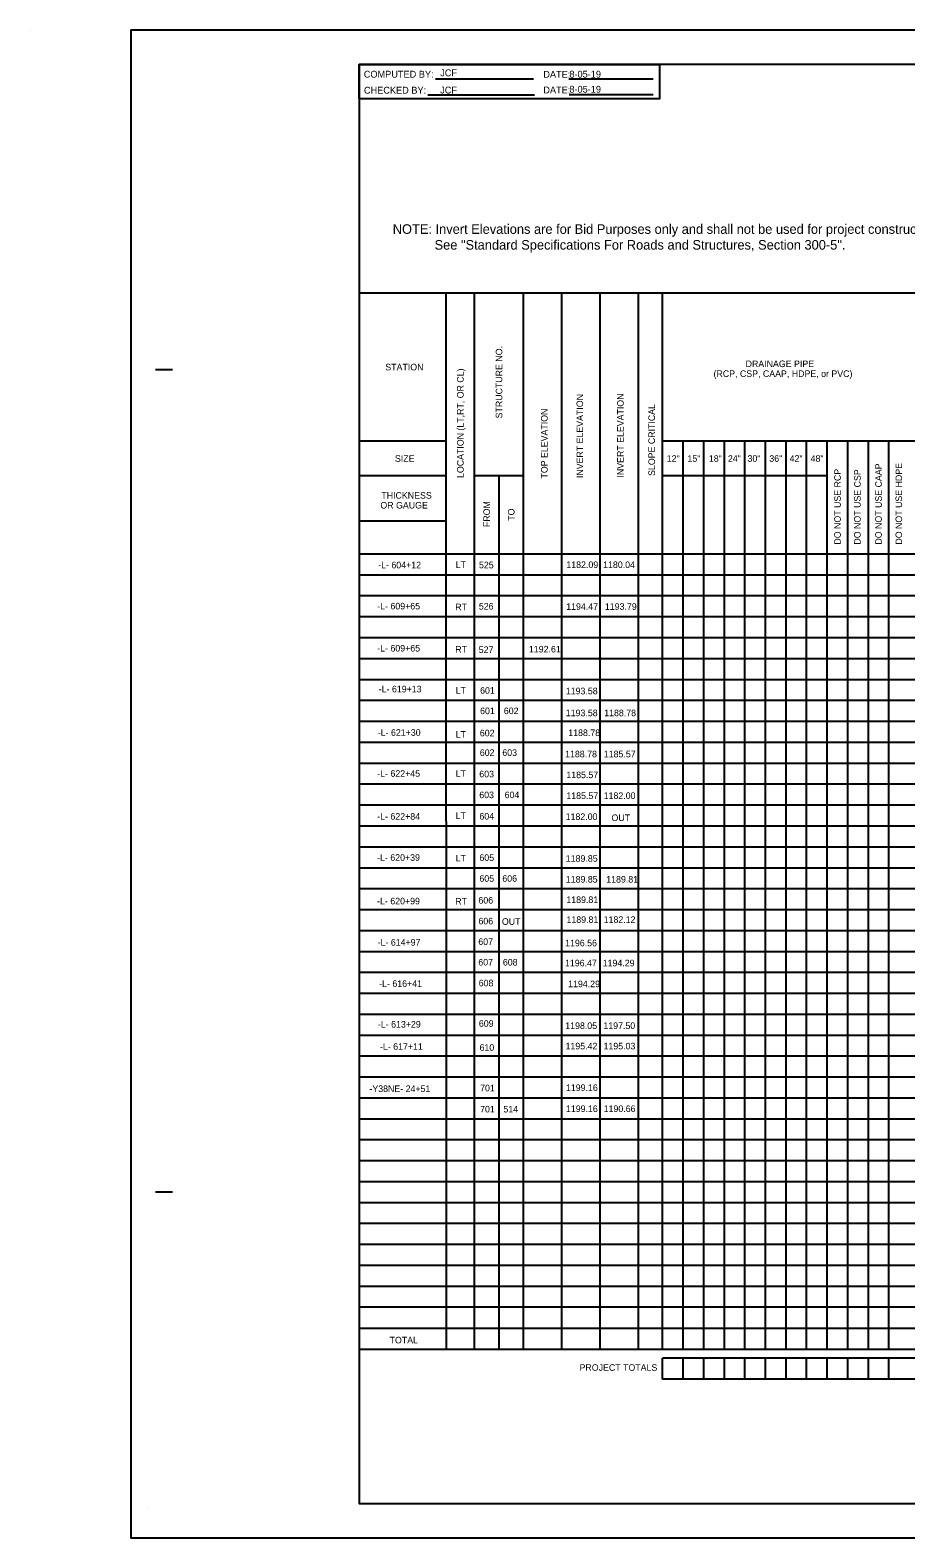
# Model space of a CAD drawing. Extents: x 809447 to 814738, y 647528 to 651206.
# Drawn here: x 812955 to 813593, y 650017 to 651117 of the extents above; entities that cross this region are included whole.
import ezdxf

# ---------------------------------------------------------------- set-up
doc = ezdxf.new("R2010")
doc.units = 0
doc.layers.add('Default', color=7, linetype='Continuous')

msp = doc.modelspace()

# ---------------------------------------------------------------- linework, layer by layer
at = {"layer": 'Default'}
for p, q in [((812954.7, 651116.9), (812954.7, 651116.9)), ((812954.7, 651116.9), (812954.7, 651116.9)), ((812954.7, 651116.9), (812954.7, 651116.9)), ((813250.2, 651081.5), (813321.8, 651081.5)), ((813347.6, 651081.4), (813409, 651081.4)), ((813244.8, 651069.8), (813322.5, 651069.8)), ((813347.7, 651069.9), (813409.1, 651069.9)), ((814694.6, 650925.1), (813194.6, 650925)), ((813258.2, 650154.3), (813258.1, 650925)), ((813278.7, 650154.3), (813278.7, 650925)), ((813314.5, 650154.3), (813314.4, 650925)), ((813342.5, 650154.3), (813342.4, 650925)), ((813370.4, 650154.3), (813370.4, 650925)), ((813398.4, 650154.3), (813398.4, 650925)), ((813415.9, 650154.3), (813415.9, 650925)), ((813046.1, 650869.4), (813058.6, 650869.4)), ((813258.1, 650817.1), (813194.6, 650817.1)), ((813933.4, 650817.2), (813415.9, 650817.1)), ((813430.9, 650154.3), (813430.9, 650817.1)), ((813445.9, 650154.3), (813445.9, 650817.1)), ((813460.9, 650154.3), (813460.9, 650817.1)), ((813475.9, 650154.3), (813475.9, 650817.1)), ((813490.9, 650154.3), (813490.9, 650817.1)), ((813505.9, 650154.3), (813505.9, 650817.1)), ((813520.9, 650154.3), (813520.9, 650817.1)), ((813535.9, 650154.3), (813535.9, 650817.1)), ((813550.9, 650154.3), (813550.9, 650817.1)), ((813565.9, 650154.3), (813565.9, 650817.1)), ((813580.9, 650154.3), (813580.9, 650817.1)), ((813258.1, 650791.7), (813194.6, 650791.7)), ((813314.5, 650791.7), (813278.7, 650791.7)), ((813296.6, 650154.3), (813296.6, 650791.7)), ((813535.9, 650791.8), (813415.9, 650791.7)), ((813258.1, 650758.6), (813194.6, 650758.6)), ((814694.6, 650734.7), (813194.6, 650734.7)), ((814694.6, 650719.4), (813194.6, 650719.4)), ((814694.6, 650704.1), (813194.6, 650704.1)), ((814694.6, 650688.9), (813194.6, 650688.9)), ((814694.6, 650673.6), (813194.6, 650673.6)), ((814694.6, 650658.3), (813194.6, 650658.3)), ((814694.6, 650643), (813194.6, 650643)), ((814694.6, 650627.8), (813194.6, 650627.8)), ((814694.6, 650612.5), (813194.6, 650612.5)), ((814694.6, 650597.3), (813194.6, 650597.3)), ((814694.6, 650582), (813194.6, 650582)), ((814694.6, 650566.7), (813194.6, 650566.7)), ((814694.6, 650551.5), (813194.6, 650551.5)), ((814694.6, 650536.2), (813194.6, 650536.2)), ((814694.6, 650520.9), (813194.6, 650520.9)), ((814694.6, 650505.6), (813194.6, 650505.6)), ((814694.6, 650490.4), (813194.6, 650490.4)), ((814694.6, 650475.1), (813194.6, 650475.1)), ((814694.6, 650459.8), (813194.6, 650459.8)), ((814694.6, 650444.5), (813194.6, 650444.5)), ((814694.6, 650429.3), (813194.6, 650429.3)), ((814694.6, 650414), (813194.6, 650414)), ((814694.6, 650398.8), (813194.6, 650398.8)), ((814694.6, 650383.5), (813194.6, 650383.5)), ((814694.6, 650368.3), (813194.6, 650368.3)), ((814694.6, 650353), (813194.6, 650353)), ((814694.6, 650337.8), (813194.6, 650337.8)), ((814694.6, 650322.5), (813194.6, 650322.5)), ((814694.6, 650307.2), (813194.6, 650307.2)), ((814694.6, 650291.9), (813194.6, 650291.9)), ((814694.6, 650276.7), (813194.6, 650276.7)), ((813046.1, 650269.4), (813058.6, 650269.4)), ((814694.6, 650261.4), (813194.6, 650261.4)), ((814694.6, 650246.2), (813194.6, 650246.2)), ((814694.6, 650230.9), (813194.6, 650230.9)), ((814694.6, 650215.7), (813194.6, 650215.7)), ((814694.6, 650200.4), (813194.6, 650200.4)), ((814694.6, 650185.2), (813194.6, 650185.2)), ((814694.6, 650169.6), (813194.6, 650169.6)), ((814694.6, 650154.3), (813194.6, 650154.3)), ((814694.6, 650154.3), (813194.6, 650154.3)), ((813415.9, 650132.8), (813415.9, 650148.1)), ((814522.5, 650148.1), (813415.9, 650148.1)), ((813430.9, 650132.8), (813430.9, 650148.1)), ((813445.9, 650132.8), (813445.9, 650148.1)), ((813460.9, 650132.8), (813460.9, 650148.1)), ((813475.9, 650132.8), (813475.9, 650148.1)), ((813490.9, 650132.8), (813490.9, 650148.1)), ((813505.9, 650132.8), (813505.9, 650148.1)), ((813520.9, 650132.8), (813520.9, 650148.1)), ((813535.9, 650132.8), (813535.9, 650148.1)), ((813550.9, 650132.8), (813550.9, 650148.1)), ((813565.9, 650132.8), (813565.9, 650148.1)), ((813580.9, 650132.8), (813580.9, 650148.1)), ((814522.5, 650132.8), (813415.9, 650132.8)), ((813041.1, 650039.4), (813041.1, 650039.4)), ((813194.6, 650041.9), (813194.6, 650041.9)), ((813194.6, 650041.9), (813194.6, 650041.9)), ((813194.6, 650041.9), (813194.6, 650041.9)), ((813194.6, 650041.9), (813194.6, 650041.9)), ((813194.6, 650041.9), (813194.6, 650041.9)), ((813194.6, 650041.9), (813194.6, 650041.9)), ((813194.6, 650041.9), (813194.6, 650041.9)), ((813194.6, 650041.9), (813194.6, 650041.9)), ((813194.6, 650041.9), (813194.6, 650041.9)), ((813028.1, 650016.9), (813028.1, 650016.9))]:
    msp.add_line(p, q, dxfattribs=at)
for points in [[(814712.1, 651116.9), (813028.1, 651116.9), (813028.1, 650016.9), (814712.1, 650016.9)], [(814694.6, 651091.9), (813194.6, 651091.9), (813194.6, 650041.9), (814694.6, 650041.9)], [(813194.6, 651091.9), (813413.6, 651091.9), (813413.6, 651066.9), (813194.6, 651066.9)]]:
    msp.add_lwpolyline(points, close=True, dxfattribs=at)

# ---------------------------------------------------------------- texts
for s, height, rotation, p in [('COMPUTED BY:', 5, 360, (813198, 651082.3)), ('JCF', 5, 360, (813253.7, 651083.3)), ('DATE:', 5, 360, (813328.9, 651082.2)), ('CHECKED BY:', 5, 360, (813198.1, 651070.6)), ('JCF', 5, 360, (813253.7, 651070.7)), ('DATE:', 5, 360, (813328.9, 651070.8)), ('STRUCTURE NO.', 4.8, 90, (813299, 650833.7)), ('STATION', 4.8, 360, (813213.7, 650868.7)), ('LOCATION (LT,RT, OR CL)', 4.8, 90, (813270.8, 650790.2)), ('INVERT ELEVATION', 4.8, 90, (813357.9, 650790.1)), ('INVERT ELEVATION', 4.8, 90, (813387.5, 650790.5)), ('TOP ELEVATION', 4.8, 90, (813332, 650789.8)), ('SLOPE CRITICAL', 4.8, 90, (813410.3, 650791.7)), ('DO NOT USE RCP', 4.8, 90, (813545.8, 650741.6)), ('DO NOT USE CSP', 4.8, 90, (813560.3, 650741.6)), ('DO NOT USE CAAP', 4.8, 90, (813575.7, 650741.6)), ('DO NOT USE HDPE', 4.8, 90, (813590.5, 650741.6)), ('FROM', 4.8, 90, (813290, 650754.4)), ('TO', 4.8, 90, (813307.9, 650759))]:
    msp.add_text(s, height=height, rotation=rotation, dxfattribs=at).set_placement(p)
for s, height, p in [('8-05-19', 5, (813347.9, 651082.3)), ('8-05-19', 5, (813347.9, 651071.3)), ('NOTE: Invert Elevations are for Bid Purposes only and shall not be used for project construction stakeout.', 7, (813219.1, 650968.3)), ('See "Standard Specifications For Roads and Structures, Section 300-5".', 7, (813249.6, 650956.8)), ('DRAINAGE PIPE', 4.8, (813476.4, 650871.1)), ('(RCP, CSP, CAAP, HDPE, or PVC)', 4.8, (813453, 650863.9)), ('SIZE', 4.8, (813220.7, 650802)), ('12"', 4.8, (813418.9, 650802)), ('15"', 4.8, (813434, 650802)), ('18"', 4.8, (813449.6, 650802)), ('24"', 4.8, (813463.5, 650802)), ('30"', 4.8, (813477.8, 650802)), ('36"', 4.8, (813493.7, 650802)), ('42"', 4.8, (813508.5, 650802)), ('48"', 4.8, (813523.8, 650802)), ('OR GAUGE', 4.8, (813210.1, 650767.9)), ('THICKNESS', 4.8, (813210.8, 650775.1)), ('-L- 604+12', 4.8, (813208.5, 650724.3)), ('LT', 4.8, (813265, 650724.6)), ('525', 4.8, (813282, 650724.3)), ('1182.09', 4.8, (813345.7, 650724.5)), ('1180.04', 4.8, (813372.5, 650724.5)), ('-L- 609+65', 4.8, (813207.8, 650694.3)), ('RT', 4.8, (813264.7, 650693.7)), ('526', 4.8, (813281.9, 650694.2)), ('1194.47', 4.8, (813345.6, 650694)), ('1193.79', 4.8, (813373.8, 650694)), ('-L- 609+65', 4.8, (813207.8, 650663.6)), ('RT', 4.8, (813264.7, 650662.8)), ('527', 4.8, (813281.8, 650662.5)), ('1192.61', 4.8, (813318.4, 650662.9)), ('-L- 619+13', 4.8, (813208.9, 650633.8)), ('LT', 4.8, (813265, 650632.9)), ('601', 4.8, (813282.8, 650632.8)), ('1193.58', 4.8, (813345.3, 650632.4)), ('601', 4.8, (813282.8, 650617.9)), ('602', 4.8, (813300.1, 650617.9)), ('1193.58', 4.8, (813345.3, 650616.4)), ('1188.78', 4.8, (813373.3, 650616.4)), ('-L- 621+30', 4.8, (813208.2, 650602.1)), ('602', 4.8, (813282.6, 650601.7)), ('1188.78', 4.8, (813347.1, 650601.9)), ('LT', 4.8, (813265, 650600.7)), ('602', 4.8, (813282.6, 650587.4)), ('603', 4.8, (813299, 650587.4)), ('1188.78', 4.8, (813344.8, 650586.4)), ('1185.57', 4.8, (813373, 650586.4)), ('-L- 622+45', 4.8, (813207.8, 650572.2)), ('LT', 4.8, (813265, 650572.2)), ('603', 4.8, (813282.2, 650571.8)), ('1185.57', 4.8, (813345.7, 650571.2)), ('603', 4.8, (813282.2, 650556.6)), ('604', 4.8, (813300.7, 650556.6)), ('1185.57', 4.8, (813345.7, 650556)), ('1182.00', 4.8, (813372.9, 650556)), ('-L- 622+84', 4.8, (813207.8, 650540.9)), ('LT', 4.8, (813265, 650541.4)), ('604', 4.8, (813282.3, 650541)), ('1182.00', 4.8, (813345.2, 650540.7)), ('OUT', 4.8, (813378.6, 650539.9)), ('-L- 620+39', 4.8, (813207.7, 650510.9)), ('LT', 4.8, (813265, 650510.4)), ('605', 4.8, (813282.3, 650510.8)), ('1189.85', 4.8, (813345.3, 650510.2)), ('605', 4.8, (813282.3, 650495.6)), ('606', 4.8, (813299, 650495.6)), ('1189.85', 4.8, (813345.3, 650495)), ('1189.81', 4.8, (813374.8, 650495)), ('-L- 620+99', 4.8, (813207.7, 650479.1)), ('RT', 4.8, (813264.7, 650479)), ('606', 4.8, (813281.6, 650479.7)), ('1189.81', 4.8, (813345.7, 650480.1)), ('606', 4.8, (813281.6, 650464.5)), ('OUT', 4.8, (813298.7, 650464.2)), ('1189.81', 4.8, (813345.8, 650465.6)), ('1182.12', 4.8, (813372.9, 650465.6)), ('-L- 614+97', 4.8, (813208.1, 650449)), ('607', 4.8, (813281.5, 650449.5)), ('1196.56', 4.8, (813344.8, 650448.5)), ('607', 4.8, (813281.5, 650434.5)), ('608', 4.8, (813299.4, 650434.5)), ('1196.47', 4.8, (813344.7, 650433.9)), ('1194.29', 4.8, (813372.2, 650433.9)), ('-L- 616+41', 4.8, (813209.2, 650418.9)), ('608', 4.8, (813281.8, 650419.3)), ('1194.29', 4.8, (813347, 650418.7)), ('-L- 613+29', 4.8, (813208.3, 650389.2)), ('609', 4.8, (813281.9, 650389.8)), ('1198.05', 4.8, (813344.9, 650388.2)), ('1197.50', 4.8, (813372.7, 650388.2)), ('-L- 617+11', 4.8, (813209.8, 650373)), ('610', 4.8, (813282.4, 650372.3)), ('1195.42', 4.8, (813345.1, 650373.3)), ('1195.03', 4.8, (813372.8, 650373.3)), ('-Y38NE- 24+51', 4.8, (813202.1, 650342.2)), ('701', 4.8, (813282.8, 650342.7)), ('1199.16', 4.8, (813345.4, 650343)), ('701', 4.8, (813282.8, 650327.3)), ('514', 4.8, (813299.8, 650327.3)), ('1199.16', 4.8, (813345.4, 650327.6)), ('1190.66', 4.8, (813372.9, 650327.6)), ('TOTAL', 4.8, (813216.8, 650158.8)), ('PROJECT TOTALS', 4.8, (813355.3, 650138.8))]:
    msp.add_text(s, height=height, dxfattribs=at).set_placement(p)

doc.saveas('drawing.dxf')
